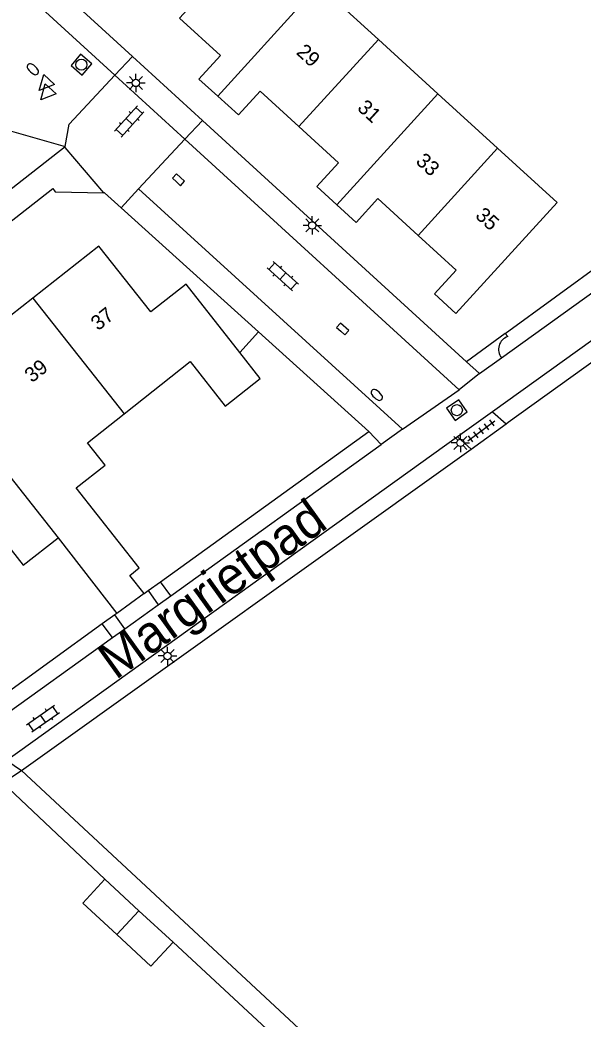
# Model space of a CAD drawing. Extents: x 136000 to 141014, y 402000 to 403500.
# Drawn here: x 137480.4 to 137518.5, y 402230.1 to 402297.7 of the extents above; entities that cross this region are included whole.
import ezdxf

# ---------------------------------------------------------------- set-up
doc = ezdxf.new("R2010")
doc.units = 0
for name, color, linetype in [('gg-afsc-erfafscheiding', 7, 'Continuous'), ('gg-afsc-hekwerk', 7, 'Continuous'), ('gg-afsc-muur', 7, 'Continuous'), ('gg-anno-huisnummerreeks BGT', 7, 'Continuous'), ('gg-anno-openbare ruimte label', 7, 'Continuous'), ('gg-bbg-gedigitaliseerde bebouwing', 7, 'Continuous'), ('gg-bbg-gedigitaliseerde bijgebouw', 7, 'Continuous'), ('gg-bbg-hoofdgebouw', 7, 'Continuous'), ('gg-bbg-tussenscheiding', 7, 'Continuous'), ('gg-knt-verharding', 7, 'Continuous'), ('gg-knt-verharding nz', 7, 'Continuous'), ('gt-grn-vlakafsluiter', 7, 'Continuous'), ('gt-grn-weggrens', 7, 'Continuous'), ('gt-symb-brandkraan', 7, 'Continuous'), ('gt-symb-klinker verharding', 7, 'Continuous'), ('gt-symb-kolk', 7, 'Continuous'), ('gt-symb-lichtmast', 7, 'Continuous'), ('gt-symb-rioolschacht', 7, 'Continuous'), ('gt-symb-tegel verharding', 7, 'Continuous'), ('gt-symb-waterafsluiter', 7, 'Continuous')]:
    doc.layers.add(name, color=color, linetype=linetype)

# ---------------------------------------------------------------- blocks, each defined once
blk = doc.blocks.new('gt0-BR')
at = {"layer": 'gt-symb-brandkraan'}
for centre, radius, start, end in [((-0.244, 0), 0.206, 107.56694, 252.43307), ((0.599, -2.664), 3, 106.89205, 107.56694), ((0, -0.691), 0.938, 73.10799, 106.89205), ((-0.599, -2.664), 3, 72.43309, 73.10799), ((0.244, 0), 0.206, 287.56695, 72.43309), ((0.599, 2.664), 3, 252.43307, 253.10797), ((0, 0.691), 0.938, 253.10797, 286.89206), ((-0.599, 2.664), 3, 286.89206, 287.56695)]:
    blk.add_arc(centre, radius, start, end, dxfattribs=at)
blk = doc.blocks.new('gt0-WAFSL')
at = {"layer": 'gt-symb-waterafsluiter'}
for p, q in [((-0.5, -0.333), (0, 0.667)), ((0, 0.667), (0.5, -0.333)), ((0.5, -0.333), (-0.5, -0.333))]:
    blk.add_line(p, q, dxfattribs=at)
blk = doc.blocks.new('gt0-RS')
at = {"layer": 'gt-symb-rioolschacht'}
blk.add_lwpolyline([(-0.5, -0.5), (0.5, -0.5), (0.5, 0.5), (-0.5, 0.5)], close=True, dxfattribs=at)
blk.add_circle((0, 0), 0.375, dxfattribs=at)
blk = doc.blocks.new('gt0-KL1')
at = {"layer": 'gt-symb-klinker verharding'}
for p, q in [((-1.15, 0.3), (1.15, 0.3)), ((-1, -0.3), (-1, 0.3)), ((-0.5, 0.3), (-0.5, 0.45)), ((0, -0.3), (0, 0.3)), ((0.5, 0.3), (0.5, 0.45)), ((1, -0.3), (1, 0.3)), ((-1.15, -0.3), (1.15, -0.3)), ((-0.5, -0.45), (-0.5, -0.3)), ((0.5, -0.45), (0.5, -0.3))]:
    blk.add_line(p, q, dxfattribs=at)
blk = doc.blocks.new('gt0-LMAST')
at = {"layer": 'gt-symb-lichtmast'}
for p, q in [((-0.182, 0.173), (-0.447, 0.438)), ((-0.005, 0.246), (-0.005, 0.621)), ((0.172, 0.173), (0.437, 0.438)), ((-0.255, -0.004), (-0.63, -0.004)), ((-0.182, -0.181), (-0.447, -0.446)), ((-0.005, -0.254), (-0.005, -0.629)), ((0.437, -0.446), (0.172, -0.181)), ((0.245, -0.004), (0.62, -0.004))]:
    blk.add_line(p, q, dxfattribs=at)
blk.add_circle((-0.005, -0.004), 0.25, dxfattribs=at)
blk = doc.blocks.new('gt0-KOLK')
at = {"layer": 'gt-symb-kolk'}
blk.add_lwpolyline([(0, 0), (0.375, 0), (0.375, 0.4), (-0.375, 0.4), (-0.375, 0), (0, 0)], dxfattribs=at)
blk = doc.blocks.new('gt0-TEG1')
at = {"layer": 'gt-symb-tegel verharding'}
for p, q in [((-1.125, 0), (1.125, 0)), ((-0.9, -0.25), (-0.9, 0.25)), ((-0.45, -0.25), (-0.45, 0.25)), ((0, -0.25), (0, 0.25)), ((0.45, -0.25), (0.45, 0.25)), ((0.9, -0.25), (0.9, 0.25))]:
    blk.add_line(p, q, dxfattribs=at)

msp = doc.modelspace()

# ---------------------------------------------------------------- linework, layer by layer
at = {"layer": 'gg-afsc-erfafscheiding'}
for p, q in [((137513.25, 402276.473), (137531.033, 402289.457)), ((137486.13, 402239.53), (137479.211, 402246.04)), ((137490.75, 402235.25), (137506.48, 402220.69))]:
    msp.add_line(p, q, dxfattribs=at)
at = {"layer": 'gg-afsc-hekwerk'}
for p, q in [((137510.943, 402268.636), (137513.299, 402270.354)), ((137513.299, 402270.354), (137513.439, 402270.456)), ((137480.481, 402246.887), (137510.943, 402268.636)), ((137480.481, 402246.887), (137515.631, 402214.233))]:
    msp.add_line(p, q, dxfattribs=at)
msp.add_lwpolyline([(137513.439, 402270.456), (137534.423, 402285.516), (137534.45, 402285.486)], dxfattribs=at)
at = {"layer": 'gg-afsc-muur'}
for p, q in [((137496.531, 402276.568), (137495.269, 402275.185)), ((137504, 402269.824), (137496.531, 402276.568)), ((137489.905, 402259.661), (137504, 402269.824)), ((137489.065, 402259.055), (137489.905, 402259.661)), ((137488.782, 402258.851), (137489.065, 402259.055)), ((137486.8, 402257.424), (137485.957, 402256.816)), ((137486.93, 402257.518), (137486.8, 402257.424)), ((137485.957, 402256.816), (137472.841, 402247.324))]:
    msp.add_line(p, q, dxfattribs=at)
at = {"layer": 'gg-bbg-gedigitaliseerde bebouwing'}
for p, q in [((137500.614, 402300.047), (137504.652, 402296.371)), ((137504.652, 402296.371), (137508.69, 402292.695)), ((137508.69, 402292.695), (137512.728, 402289.019)), ((137512.728, 402289.019), (137516.77, 402285.34)), ((137482.962, 402262.627), (137486.93, 402257.518))]:
    msp.add_line(p, q, dxfattribs=at)
msp.add_lwpolyline([(137472.51, 402261.81), (137477.003, 402265.333), (137480.6, 402260.78), (137482.962, 402262.627)], dxfattribs=at)
at = {"layer": 'gg-bbg-gedigitaliseerde bijgebouw'}
for p, q in [((137486.13, 402239.53), (137488.44, 402237.39)), ((137488.44, 402237.39), (137490.75, 402235.25))]:
    msp.add_line(p, q, dxfattribs=at)
for points in [[(137486.94, 402235.77), (137484.63, 402237.91), (137486.13, 402239.53)], [(137490.75, 402235.25), (137489.25, 402233.63), (137486.94, 402235.77)]]:
    msp.add_lwpolyline(points, dxfattribs=at)
at = {"layer": 'gg-bbg-hoofdgebouw'}
msp.add_line((137488.782, 402258.851), (137486.93, 402257.518), dxfattribs=at)
for points in [[(137493.77, 402292.533), (137492.5, 402293.68), (137493.97, 402295.29), (137491.19, 402297.81), (137493.204, 402300.028), (137490.967, 402302.071)], [(137499.273, 402290.466), (137496.64, 402292.87), (137495.18, 402291.26), (137493.77, 402292.533)], [(137501.838, 402285.174), (137500.48, 402286.41), (137501.95, 402288.02), (137499.273, 402290.466)], [(137507.341, 402283.105), (137504.62, 402285.59), (137503.15, 402283.98), (137501.838, 402285.174)], [(137516.77, 402285.34), (137509.91, 402277.82), (137508.45, 402279.14), (137509.92, 402280.75), (137507.341, 402283.105)], [(137495.269, 402275.185), (137491.63, 402279.8), (137489.25, 402277.93), (137485.73, 402282.38), (137481.245, 402278.856)], [(137481.245, 402278.856), (137476.77, 402275.34), (137479.046, 402272.448)], [(137487.432, 402271.027), (137491.913, 402274.557), (137494.279, 402271.554), (137496.655, 402273.427), (137495.269, 402275.185)], [(137488.782, 402258.851), (137487.813, 402260.079), (137488.463, 402260.591), (137484.186, 402266.019), (137486.141, 402267.558), (137484.949, 402269.071), (137487.432, 402271.027)]]:
    msp.add_lwpolyline(points, dxfattribs=at)
at = {"layer": 'gg-bbg-tussenscheiding'}
for p, q in [((137493.77, 402292.533), (137500.614, 402300.047)), ((137499.273, 402290.466), (137504.652, 402296.371)), ((137501.838, 402285.174), (137508.69, 402292.695)), ((137507.341, 402283.105), (137512.728, 402289.019)), ((137481.245, 402278.856), (137487.432, 402271.027)), ((137477.93, 402269.01), (137482.962, 402262.627)), ((137488.44, 402237.39), (137486.94, 402235.77))]:
    msp.add_line(p, q, dxfattribs=at)
at = {"layer": 'gg-knt-verharding'}
for p, q in [((137487.996, 402295.205), (137486.813, 402293.94)), ((137492.737, 402290.877), (137487.996, 402295.205)), ((137491.555, 402289.61), (137492.737, 402290.877)), ((137510.62, 402274.553), (137492.737, 402290.877)), ((137488.416, 402286.246), (137491.555, 402289.61)), ((137512.989, 402274.819), (137532.9, 402289.11)), ((137534.61, 402287.13), (137512.374, 402271.168)), ((137487.228, 402284.972), (137488.416, 402286.246)), ((137496.531, 402276.568), (137487.228, 402284.972)), ((137513.414, 402276.249), (137513.25, 402276.473)), ((137511.5, 402273.75), (137512.989, 402274.819)), ((137510.62, 402274.553), (137511.5, 402273.75)), ((137512.374, 402271.168), (137510.001, 402269.465)), ((137512.374, 402271.168), (137513.299, 402270.354)), ((137510.001, 402269.465), (137479.487, 402247.56)), ((137504.85, 402268.95), (137504, 402269.824)), ((137510.001, 402269.465), (137510.943, 402268.636)), ((137490.591, 402258.71), (137504.85, 402268.95)), ((137490.591, 402258.71), (137489.905, 402259.661)), ((137489.065, 402259.055), (137489.748, 402258.104)), ((137487.482, 402256.477), (137489.748, 402258.104)), ((137487.482, 402256.477), (137486.8, 402257.424)), ((137486.64, 402255.873), (137485.957, 402256.816)), ((137473.486, 402246.426), (137486.64, 402255.873)), ((137479.487, 402247.56), (137480.481, 402246.887))]:
    msp.add_line(p, q, dxfattribs=at)
for points in [[(137487.996, 402295.205), (137455.86, 402324.54), (137429.54, 402363.69), (137430.25, 402367.32)], [(137483.444, 402289.124), (137483.722, 402290.636), (137486.813, 402293.94)], [(137486.056, 402285.991), (137483.431, 402289.054), (137483.444, 402289.124)], [(137442.22, 402254.67), (137482.6, 402286.28), (137482.76, 402286.05), (137486.056, 402285.991)], [(137487.228, 402284.972), (137486.1, 402285.99), (137486.056, 402285.991)]]:
    msp.add_lwpolyline(points, dxfattribs=at)
msp.add_arc((137513.697, 402275.387), 0.908, 108.16933, 218.72648, dxfattribs=at)
at = {"layer": 'gg-knt-verharding nz'}
for p, q in [((137491.555, 402289.61), (137486.813, 402293.94)), ((137440.51, 402255.54), (137483.444, 402289.124)), ((137510.12, 402272.66), (137491.555, 402289.61)), ((137488.416, 402286.246), (137506.29, 402269.99)), ((137506.29, 402269.99), (137510.12, 402272.66)), ((137489.748, 402258.104), (137490.591, 402258.71)), ((137486.64, 402255.873), (137487.482, 402256.477)), ((137479.211, 402246.04), (137480.481, 402246.887))]:
    msp.add_line(p, q, dxfattribs=at)
msp.add_lwpolyline([(137486.813, 402293.94), (137454.46, 402323.48), (137427.67, 402363.33), (137428.62, 402368.21)], dxfattribs=at)
at = {"layer": 'gt-grn-vlakafsluiter'}
msp.add_line((137513.25, 402276.473), (137510.62, 402274.553), dxfattribs=at)
at = {"layer": 'gt-grn-weggrens'}
for p, q in [((137477.97, 402290.68), (137483.444, 402289.124)), ((137511.5, 402273.75), (137510.12, 402272.66)), ((137506.29, 402269.99), (137504.85, 402268.95))]:
    msp.add_line(p, q, dxfattribs=at)

# ---------------------------------------------------------------- block references
at = {"layer": 'gt-symb-brandkraan'}
for p, rotation in [((137481.254, 402294.352), 137.63383016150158), ((137504.546, 402272.305), 137.75715663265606)]:
    msp.add_blockref('gt0-BR', p, dxfattribs=dict(at, rotation=rotation))
at = {"layer": 'gt-symb-klinker verharding'}
for p, rotation in [((137487.785, 402290.816), -132.12343818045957), ((137498.185, 402280.35), -42.285248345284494), ((137481.947, 402250.39), 34.73862528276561)]:
    msp.add_blockref('gt0-KL1', p, dxfattribs=dict(at, rotation=rotation))
at = {"layer": 'gt-symb-kolk', "rotation": -42.36616983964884}
for p in [(137490.985, 402286.722), (137502.103, 402276.62)]:
    msp.add_blockref('gt0-KOLK', p, dxfattribs=at)
at = {"layer": 'gt-symb-lichtmast'}
for p in [(137488.236, 402293.426), (137500.18, 402283.783), (137510.216, 402269.062), (137490.378, 402254.636)]:
    msp.add_blockref('gt0-LMAST', p, dxfattribs=at)
at = {"layer": 'gt-symb-rioolschacht'}
for p, rotation in [((137484.543, 402294.659), -40.7007448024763), ((137509.968, 402271.273), 34.898123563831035)]:
    msp.add_blockref('gt0-RS', p, dxfattribs=dict(at, rotation=rotation))
at = {"layer": 'gt-symb-tegel verharding', "rotation": 36.4231783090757}
msp.add_blockref('gt0-TEG1', (137511.626, 402269.875), dxfattribs=at)
at = {"layer": 'gt-symb-waterafsluiter'}
for p, rotation in [((137482.132, 402293.415), 137.63383016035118), ((137482.232, 402292.783), 137.63383015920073)]:
    msp.add_blockref('gt0-WAFSL', p, dxfattribs=dict(at, rotation=rotation))

# ---------------------------------------------------------------- texts
at = {"layer": 'gg-anno-huisnummerreeks BGT'}
for s, rotation, p in [('29', 317.6, (137499.03, 402295.428)), ('31', 317.6, (137503.166, 402291.65)), ('33', 317.6, (137507.125, 402288.043)), ('35', 317.6, (137511.157, 402284.361)), ('37', 38.2, (137485.673, 402276.613)), ('39', 38.2, (137481.19, 402273.09))]:
    msp.add_text(s, height=1, rotation=rotation, dxfattribs=at).set_placement(p)
at = {"layer": 'gg-anno-openbare ruimte label'}
msp.add_text('Margrietpad', height=2.5, rotation=35.7, dxfattribs=at).set_placement((137486.857, 402252.967))

doc.saveas('drawing.dxf')
